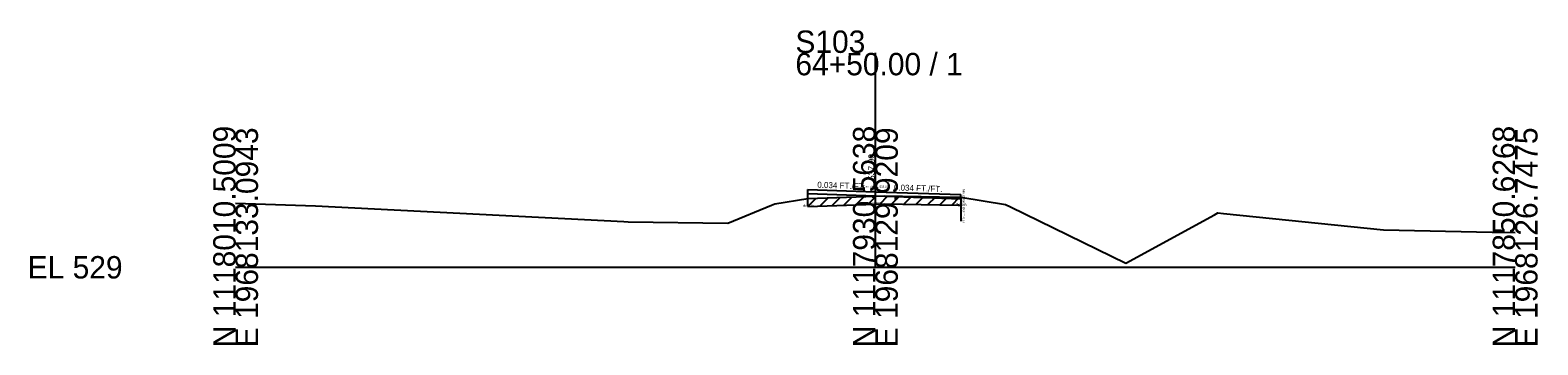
# Model space of a CAD drawing. Extents: x -26 to 163, y -10 to 24018.
# Drawn here: x -25.7 to 162.8, y 12490.3 to 12529.6 of the extents above; entities that cross this region are included whole.
import ezdxf

# ---------------------------------------------------------------- set-up
doc = ezdxf.new("R2010")
doc.units = 0
for name, color, linetype in [('RD_GPK_XS_Cell', 7, 'Continuous'), ('RD_XS_ExGround', 7, 'Continuous'), ('RD_XS_ExPaveRet', 7, 'Continuous'), ('RD_XS_Misc_Line', 7, 'Continuous'), ('RD_XS_PaveOvlay_CP', 7, 'Continuous'), ('RD_XS_TX_Elev_EX', 7, 'Continuous'), ('RD_XS_TX_ExEOP', 7, 'Continuous'), ('RD_XS_TX_Notes', 7, 'Continuous'), ('RD_XS_TX_Profile', 7, 'Continuous'), ('RD_XS_TX_Slope', 7, 'Continuous')]:
    doc.layers.add(name, color=color, linetype=linetype)

msp = doc.modelspace()

# ---------------------------------------------------------------- linework, layer by layer
at = {"layer": 'RD_GPK_XS_Cell'}
for p, q in [((80, 12500), (80, 12526.8)), ((0, 12500), (80, 12500)), ((80, 12500), (160, 12500))]:
    msp.add_line(p, q, dxfattribs=at)
at = {"layer": 'RD_XS_ExGround'}
msp.add_lwpolyline([(0, 12508.03), (9.99, 12507.67), (48.53, 12505.71), (49.08, 12505.68), (61.56, 12505.53), (67, 12507.76), (67.44, 12507.94), (71.55, 12508.59), (80, 12508.9), (81.11, 12508.93), (90.34, 12508.77), (90.68, 12508.76), (96.27, 12507.85), (96.91, 12507.56), (111.32, 12500.53), (122.39, 12506.54), (122.83, 12506.79), (123.52, 12506.71), (143.52, 12504.7), (157.13, 12504.38), (160, 12504.36)], dxfattribs=at)
at = {"layer": 'RD_XS_ExPaveRet'}
for p, q in [((71.55, 12507.59), (72.59, 12508.63)), ((71.55, 12507.59), (71.55, 12508.59)), ((71.55, 12507.59), (80, 12507.9)), ((73.05, 12507.64), (74.09, 12508.68)), ((74.55, 12507.7), (75.59, 12508.74)), ((76.05, 12507.75), (77.09, 12508.79)), ((77.55, 12507.81), (78.59, 12508.84)), ((79.05, 12507.86), (80.09, 12508.9)), ((80, 12507.9), (81.11, 12507.93)), ((80.55, 12507.91), (81.56, 12508.93)), ((81.11, 12507.93), (90.34, 12507.77)), ((82.05, 12507.92), (83.03, 12508.9)), ((83.55, 12507.89), (84.53, 12508.87)), ((85.05, 12507.86), (86.04, 12508.85)), ((86.55, 12507.84), (87.54, 12508.82)), ((88.05, 12507.81), (89.04, 12508.79)), ((89.55, 12507.78), (90.54, 12508.77)), ((90.34, 12507.77), (90.68, 12507.76)), ((90.68, 12508.76), (90.68, 12507.76))]:
    msp.add_line(p, q, dxfattribs=at)
at = {"layer": 'RD_XS_Misc_Line'}
msp.add_line((90.68, 12508.76), (90.68, 12505.76), dxfattribs=at)
at = {"layer": 'RD_XS_PaveOvlay_CP'}
for p, q in [((71.55, 12509.74), (80, 12509.45)), ((71.55, 12508.59), (71.55, 12509.74)), ((80, 12508.9), (71.55, 12509.19)), ((80, 12509.45), (90.68, 12509.08)), ((90.68, 12508.53), (80, 12508.9)), ((90.68, 12508.76), (90.68, 12509.08))]:
    msp.add_line(p, q, dxfattribs=at)

# ---------------------------------------------------------------- texts
at = {"layer": 'RD_GPK_XS_Cell'}
for s, p in [('S103', (70, 12526.8)), ('64+50.00 / 1', (70, 12524)), ('EL 529', (-26, 12498.6))]:
    msp.add_text(s, height=2.8, dxfattribs=at).set_placement(p)
for s, p in [('N 1118010.5009', (0, 12490)), ('E 1968133.0943', (2.8, 12490)), ('N 1117930.5638', (80, 12490)), ('E 1968129.9209', (82.8, 12490)), ('N 1117850.6268', (160, 12490)), ('E 1968126.7475', (162.8, 12490))]:
    msp.add_text(s, height=2.8, rotation=90, dxfattribs=at).set_placement(p)
at = {"layer": 'RD_XS_TX_Elev_EX'}
msp.add_text('537.90', height=0.8, rotation=90, dxfattribs=at).set_placement((79.9, 12510.9))
at = {"layer": 'RD_XS_TX_ExEOP'}
for s, p in [('EOP-L', (71.5, 12509.74)), ('EOP-R', (90.63, 12509.08))]:
    msp.add_text(s, height=0.1, rotation=270, dxfattribs=at).set_placement(p)
at = {"layer": 'RD_XS_TX_Notes'}
for s, p in [('Elev. @CL = 538.45', (78.48, 12509.95)), (' dE= 1.15', (70.84, 12507.59)), (' dE= 0.55', (79.29, 12507.9)), (' dE= 0.32', (89.97, 12507.76))]:
    msp.add_text(s, height=0.25, dxfattribs=at).set_placement(p)
msp.add_text(' Min. Distance @CP = -0.23', height=0.25, rotation=270, dxfattribs=at).set_placement((90.93, 12509.85))
at = {"layer": 'RD_XS_TX_Profile'}
msp.add_text('CL', height=0.25, dxfattribs=at).set_placement((79.77, 12509.45))
at = {"layer": 'RD_XS_TX_Slope'}
for p in [(72.73, 12509.95), (82.3, 12509.62)]:
    msp.add_text('0.034 FT./FT.', height=0.75, rotation=358.0353, dxfattribs=at).set_placement(p)

doc.saveas('drawing.dxf')
